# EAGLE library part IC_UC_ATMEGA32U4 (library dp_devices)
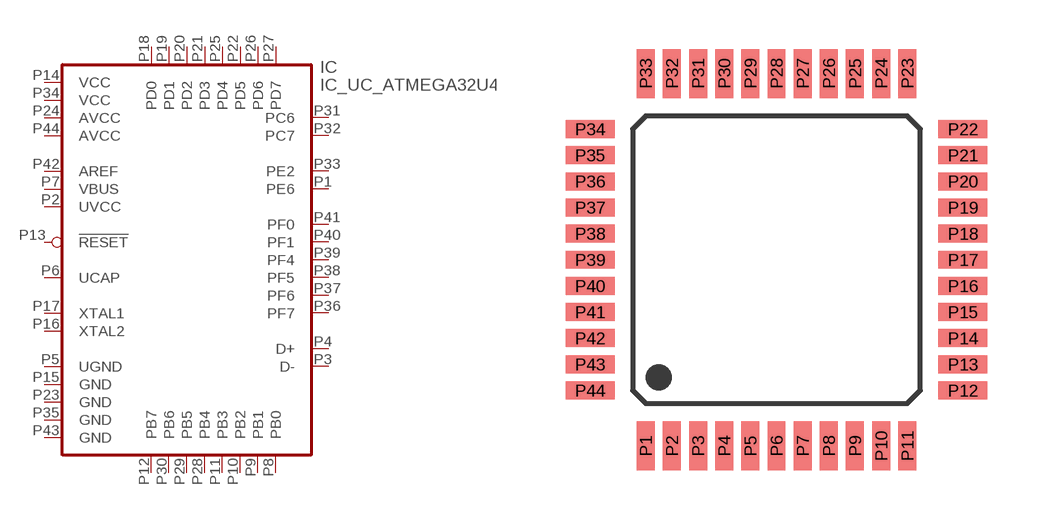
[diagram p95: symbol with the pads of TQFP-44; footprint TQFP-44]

Designator prefix IC

## IC_UC_ATMEGA32U4-TQFP44  [TQFP-44]
P1  PE6
P2  UVCC  pwr
P3  D-
P4  D+
P5  UGND  pwr
P6  UCAP  pwr
P7  VBUS  pwr
P8  PB0
P9  PB1
P10  PB2
P11  PB3
P12  PB7
P13  !RESET  in
P14  VCC  pwr
P15  GND  pwr
P16  XTAL2
P17  XTAL1
P18  PD0
P19  PD1
P20  PD2
P21  PD3
P22  PD5
P23  GND  pwr
P24  AVCC  pwr
P25  PD4
P26  PD6
P27  PD7
P28  PB4
P29  PB5
P30  PB6
P31  PC6
P32  PC7
P33  PE2
P34  VCC  pwr
P35  GND  pwr
P36  PF7
P37  PF6
P38  PF5
P39  PF4
P40  PF1
P41  PF0
P42  AREF  pwr
P43  GND  pwr
P44  AVCC  pwr

## Footprint TQFP-44 (pad centres in mm)
smd 0.55 x 1.5: P1 -4,-5.7; P2 -3.2,-5.7; P3 -2.4,-5.7; P4 -1.6,-5.7; P5 -0.8,-5.7; P6 0,-5.7; P7 0.8,-5.7; P8 1.6,-5.7; P9 2.4,-5.7; P10 3.2,-5.7; P11 4,-5.7; P23 4,5.7; P24 3.2,5.7; P25 2.4,5.7; P26 1.6,5.7; P27 0.8,5.7; P28 0,5.7; P29 -0.8,5.7; P30 -1.6,5.7; P31 -2.4,5.7; P32 -3.2,5.7; P33 -4,5.7
smd 1.5 x 0.55: P12 5.7,-4; P13 5.7,-3.2; P14 5.7,-2.4; P15 5.7,-1.6; P16 5.7,-0.8; P17 5.7,0; P18 5.7,0.8; P19 5.7,1.6; P20 5.7,2.4; P21 5.7,3.2; P22 5.7,4; P34 -5.7,4; P35 -5.7,3.2; P36 -5.7,2.4; P37 -5.7,1.6; P38 -5.7,0.8; P39 -5.7,0; P40 -5.7,-0.8; P41 -5.7,-1.6; P42 -5.7,-2.4; P43 -5.7,-3.2; P44 -5.7,-4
